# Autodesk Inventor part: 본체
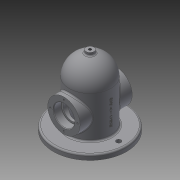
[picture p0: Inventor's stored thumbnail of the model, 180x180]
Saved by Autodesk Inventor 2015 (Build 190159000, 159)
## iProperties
Created: 2019-11
Part Number: 본체
Material: 일반
Document SubType Name: Modeling
Designer: Administrator
Density: 1 g/cm^3
Appearance: 기본값
Author: Administrator
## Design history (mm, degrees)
sketch "스케치1"
  geometry: C1 r 70 at (0, 0); 1 further point
  constraints: 1 centre point, 1 coincident
  dimensions: "d0" = 140 diameter of C1
extrude "돌출1" new body sketch "스케치1" distance "d1" = 10; taper "d2" = 0 deg
sketch "스케치2"
  geometry: C1 r 40 at (0, 0); 1 further point
  constraints: 1 centre point, 1 coincident
  dimensions: "d3" = 80 diameter of C1
extrude "돌출2" join sketch "스케치2" distance "d4" = 80; taper "d5" = 0 deg
sketch "스케치3"
  geometry: L1 (90, -40)-(90, 40) reference; L2 (10, 40)-(10, -40) reference; L3 (90, 0)-(130, 0); L4 (90, 0)-(90, -40); A1 r 40 centre (90, 0) between (90, -40) and (130, 0); 1 further point
  constraints: 5 end point, 2 point on circle, 1 centre point, 1 coincident, 1 horizontal, 1 midpoint, 1 vertical
revolve "회전1" sketch "스케치3" stored, may be unused: angle "d7" = 90 deg
node "작업 평면1"
sketch "스케치4"
  geometry: C1 r 7.5 at (0, 0); 1 further point
  constraints: 1 centre point, 1 coincident
  dimensions: "d9" = 15 diameter of C1
extrude "돌출3" join sketch "스케치4" distance "d10" = 17; taper "d11" = 0 deg
sketch "스케치7"
  geometry: C1 r 31 at (0, 50); 1 further point
  constraints: 1 centre point, 1 vertical alignment
  dimensions: "d17" = 62 diameter of C1; "d18" = 50 distance of point (0, 0) C1.centre
extrude "돌출5" join sketch "스케치7" stored distance "d19" = 100; taper "d20" = 0 deg
sketch "스케치8"
  geometry: C1 r 30 at (0, 0); 1 further point
  constraints: 1 centre point, 1 coincident
  dimensions: "d21" = 60 diameter of C1
extrude "돌출6" cut sketch "스케치8" distance "d22" = 90; taper "d23" = 0 deg
sketch "스케치9"
  geometry: L1 (90, -30)-(90, 30) reference; L2 (90, 0)-(120, 0); L3 (90, 0)-(90, -30); A1 r 30 centre (90, 0) between (90, -30) and (120, 0); 1 further point
  constraints: 6 end point, 2 point on circle, 1 centre point, 1 collinear, 1 horizontal, 1 midpoint
revolve "회전3" sketch "스케치9" stored, may be unused: angle "d25" = 90 deg
sketch "스케치10"
  geometry: C1 r 31 at (0, 0) reference; C2 r 20 at (0, 0); 1 further point
  constraints: 1 centre point, 1 coincident
  dimensions: "d26" = 40 diameter of C2
extrude "돌출7" cut sketch "스케치10" distance "d27" = 15; taper "d28" = 0 deg
sketch "스케치11"
  geometry: C1 r 31 at (0, 0) reference; C2 r 20 at (0, 0); 1 further point
  constraints: 1 centre point, 1 coincident
  dimensions: "d29" = 40 diameter of C2
extrude "돌출8" cut sketch "스케치11" distance "d30" = 15; taper "d31" = 0 deg
sketch "스케치12"
  geometry: C1 r 20 at (0, 0) reference; C2 r 16.5 at (0, 0); 1 further point
  constraints: 1 centre point, 1 coincident
  dimensions: "d32" = 33 diameter of C2
extrude "돌출9" cut sketch "스케치12" distance "d33" = 111.25; taper "d34" = 0 deg
fillet "모깎기1" dims "d35" = 0.3
sketch "스케치13"
  geometry: C1 r 31 at (0, 0) reference; 2 further points
  constraints: 1 vertical alignment
  dimensions: "d36" = 26 distance of point (0, 26) C1.centre
hole "구멍1" sketch "스케치13" at (0, 26) diameter "d37" = 3.242; stored, may be unused: countersink angle "d41" = 90 deg, drill point angle "d43" = 118 deg; dims "d38" = 8, "d39" = 4, "d40" = 2, "d42" = 10
sketch "스케치14"
  geometry: C1 r 31 at (0, 0) reference; 2 further points
  constraints: 1 vertical alignment
  dimensions: "d47" = 26 distance of point (0, 26) C1.centre
hole "구멍2" sketch "스케치14" at (0, 26) diameter "d48" = 3.242; stored, may be unused: countersink angle "d52" = 90 deg, drill point angle "d54" = 118 deg; dims "d49" = 8, "d50" = 4, "d51" = 2, "d53" = 10
chamfer "모따기1" distance "d58" = 1; stored, may be unused: second distance "d59" = 2, angle "d60" = 45 deg
hole "구멍3" diameter "d63" = 5.188; stored, may be unused: countersink angle "d67" = 90 deg, drill point angle "d69" = 118 deg; dims "d61" = 10, "d62" = 10, "d64" = 90, "d65" = 4, "d66" = 2, "d68" = 93.75
fillet "모깎기2" dims "d70" = 3
sketch "스케치15"
  geometry: A1 r 55 centre (0, 0) between (55, 0) and (-55, 0); 1 further point
  constraints: 2 horizontal alignment, 2 point on circle, 1 centre point, 1 coincident
  dimensions: "d71" = 110 diameter of A1
hole "구멍4" sketch "스케치15" at (55, 0), (-55, 0) diameter "d72" = 9; stored, may be unused: countersink angle "d76" = 90 deg, drill point angle "d78" = 118 deg; dims "d73" = 90, "d74" = 4, "d75" = 2, "d77" = 10
node "작업 평면2"
sketch "스케치16"
  geometry: L1 (-10, 70)-(-10, -70) reference; 2 further points
  constraints: 1 horizontal alignment, 1 other
  dimensions: "d79" = 50 distance from line of point (40, 0) L1
feature "엠보싱1" sketch "스케치16" dims "d80" = 0.5, "d81" = 0
node "솔리드1"
pattern_circular "원형 패턴1" dims angle "d45" = 360 deg
pattern_circular "원형 패턴2" dims angle "d56" = 360 deg
node "투영된 루프1"
node "투영된 루프2"
node "투영된 루프3"
node "투영된 루프4"
other parameters: "d8" = 135
